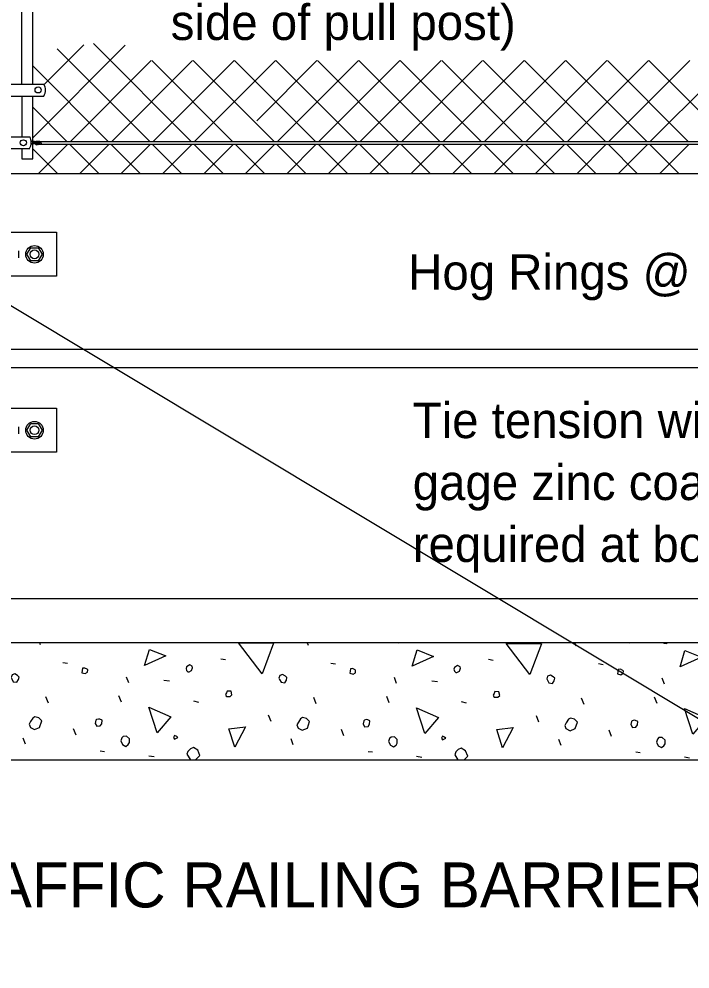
# Model space of a CAD drawing. Extents: x 110698 to 110915, y 110390 to 110472.
# Drawn here: x 110885.02 to 110888.84, y 110456.42 to 110461.82 of the extents above; entities that cross this region are included whole.
import ezdxf

# ---------------------------------------------------------------- set-up
doc = ezdxf.new("R2010")
doc.units = 0
for name, color, linetype in [('Border', 7, 'Continuous'), ('PlotBorder_dp', 7, 'Continuous'), ('SheetBorder_dp', 7, 'Continuous'), ('SheetLines_dp', 7, 'Continuous'), ('SupstrConc_h', 7, 'Continuous'), ('TextMisc', 7, 'Continuous')]:
    doc.layers.add(name, color=color, linetype=linetype)

msp = doc.modelspace()

# ---------------------------------------------------------------- linework, layer by layer
at = {"layer": 'SheetBorder_dp'}
for p, q in [((110885.1002, 110461.1484), (110885.626, 110461.6742)), ((110885.166, 110461.4498), (110885.3915, 110461.6754)), ((110885.2392, 110461.6536), (110885.766, 110461.1268)), ((110885.4454, 110461.6831), (110886.0017, 110461.1268)), ((110885.1002, 110461.5569), (110885.5303, 110461.1268)), ((110885.3143, 110461.1268), (110885.7745, 110461.587)), ((110885.55, 110461.1268), (110886.0102, 110461.587)), ((110885.7773, 110461.587), (110886.2374, 110461.1268)), ((110885.7857, 110461.1268), (110886.2459, 110461.587)), ((110886.013, 110461.587), (110886.4731, 110461.1268)), ((110886.0214, 110461.1268), (110886.4816, 110461.587)), ((110886.2487, 110461.587), (110886.7088, 110461.1268)), ((110886.375, 110461.2446), (110886.7173, 110461.587)), ((110886.4844, 110461.587), (110886.9445, 110461.1268)), ((110886.4928, 110461.1268), (110886.953, 110461.587)), ((110886.7201, 110461.587), (110887.1802, 110461.1268)), ((110886.7285, 110461.1268), (110887.1887, 110461.587)), ((110886.9558, 110461.587), (110887.4159, 110461.1268)), ((110886.9642, 110461.1268), (110887.4244, 110461.587)), ((110887.1915, 110461.587), (110887.6516, 110461.1268)), ((110887.1999, 110461.1268), (110887.6601, 110461.587)), ((110887.4272, 110461.587), (110887.8873, 110461.1268)), ((110887.4356, 110461.1268), (110887.8958, 110461.587)), ((110887.6629, 110461.587), (110888.1231, 110461.1268)), ((110887.6713, 110461.1268), (110888.1315, 110461.587)), ((110887.8986, 110461.587), (110888.3588, 110461.1268)), ((110887.907, 110461.1268), (110888.3672, 110461.587)), ((110888.1343, 110461.587), (110888.5945, 110461.1268)), ((110888.1427, 110461.1268), (110888.6029, 110461.587)), ((110888.37, 110461.587), (110888.8302, 110461.1268)), ((110888.3784, 110461.1268), (110888.8386, 110461.587)), ((110888.6057, 110461.587), (110889.0659, 110461.1268)), ((110888.6141, 110461.1268), (110889.0734, 110461.5861)), ((110885.1002, 110461.3212), (110885.2946, 110461.1268)), ((110885.1329, 110460.9454), (110885.2996, 110461.112)), ((110885.3094, 110461.112), (110885.476, 110460.9454)), ((110885.3686, 110460.9454), (110885.5353, 110461.112)), ((110885.5451, 110461.112), (110885.7117, 110460.9454)), ((110885.6043, 110460.9454), (110885.771, 110461.112)), ((110885.7808, 110461.112), (110885.9474, 110460.9454)), ((110885.84, 110460.9454), (110886.0067, 110461.112)), ((110886.0165, 110461.112), (110886.1831, 110460.9454)), ((110886.0757, 110460.9454), (110886.2424, 110461.112)), ((110886.2522, 110461.112), (110886.4188, 110460.9454)), ((110886.3114, 110460.9454), (110886.4781, 110461.112)), ((110886.4879, 110461.112), (110886.6546, 110460.9454)), ((110886.5471, 110460.9454), (110886.7138, 110461.112)), ((110886.7236, 110461.112), (110886.8903, 110460.9454)), ((110886.7828, 110460.9454), (110886.9495, 110461.112)), ((110886.9593, 110461.112), (110887.126, 110460.9454)), ((110887.0185, 110460.9454), (110887.1852, 110461.112)), ((110887.195, 110461.112), (110887.3617, 110460.9454)), ((110887.2542, 110460.9454), (110887.4209, 110461.112)), ((110887.4307, 110461.112), (110887.5974, 110460.9454)), ((110887.4899, 110460.9454), (110887.6566, 110461.112)), ((110887.6664, 110461.112), (110887.8331, 110460.9454)), ((110887.7256, 110460.9454), (110887.8923, 110461.112)), ((110887.9021, 110461.112), (110888.0688, 110460.9454)), ((110887.9613, 110460.9454), (110888.128, 110461.112)), ((110888.1378, 110461.112), (110888.3045, 110460.9454)), ((110888.197, 110460.9454), (110888.3637, 110461.112)), ((110888.3735, 110461.112), (110888.5402, 110460.9454)), ((110888.4327, 110460.9454), (110888.5994, 110461.112)), ((110888.6092, 110461.112), (110888.7759, 110460.9454)), ((110888.6684, 110460.9454), (110888.8351, 110461.112)), ((110885.1002, 110461.0855), (110885.2403, 110460.9454)), ((110885.145, 110458.2646), (110885.1398, 110458.2787)), ((110886.6689, 110458.261), (110886.6623, 110458.2787)), ((110888.1927, 110458.2575), (110888.1849, 110458.2787)), ((110888.4879, 110458.2787), (110888.495, 110458.2769)), ((110885.2723, 110458.1656), (110885.2988, 110458.1603)), ((110886.1703, 110458.1868), (110886.1969, 110458.1815)), ((110886.7961, 110458.162), (110886.8226, 110458.1567)), ((110887.6942, 110458.1832), (110887.7207, 110458.1779)), ((110888.3199, 110458.1585), (110888.3465, 110458.1532)), ((110885.6471, 110458.0489), (110885.6347, 110458.0825)), ((110885.8468, 110458.0648), (110885.8787, 110458.0613)), ((110887.1709, 110458.0454), (110887.1585, 110458.0789)), ((110887.3707, 110458.0613), (110887.4025, 110458.0577)), ((110888.6947, 110458.0418), (110888.6823, 110458.0754)), ((110885.1892, 110457.934), (110885.1751, 110457.9693)), ((110885.6047, 110457.9393), (110885.5905, 110457.9746)), ((110886.0148, 110457.9464), (110886.0431, 110457.9393)), ((110886.713, 110457.9305), (110886.6989, 110457.9658)), ((110887.1285, 110457.9358), (110887.1143, 110457.9711)), ((110887.5386, 110457.9428), (110887.5669, 110457.9358)), ((110888.2369, 110457.9269), (110888.2227, 110457.9623)), ((110888.6523, 110457.9322), (110888.6381, 110457.9676)), ((110886.4567, 110457.8297), (110886.4426, 110457.865)), ((110887.9805, 110457.8262), (110887.9664, 110457.8615)), ((110885.3466, 110457.7519), (110885.3324, 110457.7873)), ((110886.8704, 110457.7484), (110886.8562, 110457.7837)), ((110888.3942, 110457.7448), (110888.3801, 110457.7802)), ((110885.0584, 110457.7006), (110885.046, 110457.7342)), ((110886.5822, 110457.6971), (110886.5699, 110457.7307)), ((110888.106, 110457.6936), (110888.0937, 110457.7272)), ((110885.4844, 110457.6635), (110885.5092, 110457.66)), ((110887.0083, 110457.66), (110887.033, 110457.6565)), ((110888.5321, 110457.6565), (110888.5568, 110457.6529)), ((110885.7602, 110457.6352), (110885.7903, 110457.6299)), ((110887.284, 110457.6317), (110887.3141, 110457.6264)), ((110888.8078, 110457.6282), (110888.8379, 110457.6229))]:
    msp.add_line(p, q, dxfattribs=at)
for points in [[(110886.4055, 110458.1002), (110886.2711, 110458.2769), (110886.4709, 110458.2752), (110886.4055, 110458.1002)], [(110887.1674, 110458.2787), (110887.1797, 110458.2769), (110887.1839, 110458.2787)], [(110887.9293, 110458.0966), (110887.7949, 110458.2734), (110887.9947, 110458.2716), (110887.9293, 110458.0966)], [(110888.6876, 110458.2787), (110888.6912, 110458.2752)], [(110888.6912, 110458.2752), (110888.7036, 110458.2734), (110888.7159, 110458.2787)], [(110885.7355, 110458.1479), (110885.7638, 110458.2398), (110885.8574, 110458.2027), (110885.7355, 110458.1479)], [(110887.2593, 110458.1444), (110887.2876, 110458.2363), (110887.3813, 110458.1992), (110887.2593, 110458.1444)], [(110888.7831, 110458.1408), (110888.8114, 110458.2327), (110888.9051, 110458.1956), (110888.7831, 110458.1408)], [(110885.983, 110458.1125), (110885.99, 110458.1125), (110886.0042, 110458.1196), (110886.0095, 110458.1355), (110886.0077, 110458.1444), (110885.9936, 110458.1514), (110885.9759, 110458.1408), (110885.9724, 110458.1302), (110885.9759, 110458.1196), (110885.983, 110458.1125)], [(110887.5068, 110458.109), (110887.5138, 110458.109), (110887.528, 110458.1161), (110887.5333, 110458.132), (110887.5315, 110458.1408), (110887.5174, 110458.1479), (110887.4997, 110458.1373), (110887.4962, 110458.1267), (110887.4997, 110458.1161), (110887.5068, 110458.109)], [(110884.9806, 110458.0719), (110884.9895, 110458.056), (110885.0107, 110458.0524), (110885.0195, 110458.0683), (110885.0231, 110458.0825), (110885.0142, 110458.0913), (110884.9983, 110458.1002), (110884.9824, 110458.0949), (110884.9771, 110458.0789), (110884.9806, 110458.0719)], [(110885.3801, 110458.1072), (110885.3996, 110458.1019), (110885.412, 110458.1108), (110885.4137, 110458.1231), (110885.4102, 110458.1267), (110885.3961, 110458.1337), (110885.3837, 110458.132), (110885.3819, 110458.1196), (110885.3801, 110458.1072)], [(110886.5044, 110458.0683), (110886.5133, 110458.0524), (110886.5345, 110458.0489), (110886.5433, 110458.0648), (110886.5469, 110458.0789), (110886.538, 110458.0878), (110886.5221, 110458.0966), (110886.5062, 110458.0913), (110886.5009, 110458.0754), (110886.5044, 110458.0683)], [(110886.904, 110458.1037), (110886.9234, 110458.0984), (110886.9358, 110458.1072), (110886.9376, 110458.1196), (110886.934, 110458.1231), (110886.9199, 110458.1302), (110886.9075, 110458.1284), (110886.9057, 110458.1161), (110886.904, 110458.1037)], [(110888.0283, 110458.0648), (110888.0371, 110458.0489), (110888.0583, 110458.0454), (110888.0672, 110458.0613), (110888.0707, 110458.0754), (110888.0619, 110458.0843), (110888.0459, 110458.0931), (110888.03, 110458.0878), (110888.0247, 110458.0719), (110888.0283, 110458.0648)], [(110888.4278, 110458.1002), (110888.4472, 110458.0949), (110888.4596, 110458.1037), (110888.4614, 110458.1161), (110888.4578, 110458.1196), (110888.4437, 110458.1267), (110888.4313, 110458.1249), (110888.4295, 110458.1125), (110888.4278, 110458.1002)], [(110886.2022, 110457.9711), (110886.2234, 110457.9711), (110886.234, 110457.9817), (110886.2287, 110458.0012), (110886.2057, 110458.0029), (110886.2022, 110457.9923), (110886.1969, 110457.9835), (110886.2022, 110457.9711), (110886.1986, 110457.9746)], [(110887.726, 110457.9676), (110887.7472, 110457.9676), (110887.7578, 110457.9782), (110887.7525, 110457.9976), (110887.7295, 110457.9994), (110887.726, 110457.9888), (110887.7207, 110457.98), (110887.726, 110457.9676), (110887.7224, 110457.9711)], [(110885.8079, 110457.7643), (110885.7602, 110457.911), (110885.8857, 110457.8562), (110885.8079, 110457.7643)], [(110887.3318, 110457.7607), (110887.284, 110457.9075), (110887.4095, 110457.8527), (110887.3318, 110457.7607)], [(110888.8556, 110457.7572), (110888.8078, 110457.9039), (110888.9334, 110457.8491), (110888.8556, 110457.7572)], [(110885.0867, 110457.7961), (110885.1097, 110457.7837), (110885.1397, 110457.7961), (110885.1521, 110457.8332), (110885.1344, 110457.8509), (110885.1114, 110457.8562), (110885.1008, 110457.8491), (110885.0885, 110457.8297), (110885.0796, 110457.8138), (110885.0867, 110457.7961)], [(110885.4562, 110457.8191), (110885.465, 110457.8032), (110885.4844, 110457.8049), (110885.4933, 110457.8173), (110885.4951, 110457.8368), (110885.4827, 110457.8421), (110885.4738, 110457.8438), (110885.4632, 110457.8403), (110885.4597, 110457.8368), (110885.4562, 110457.8191)], [(110886.6105, 110457.7926), (110886.6335, 110457.7802), (110886.6635, 110457.7926), (110886.6759, 110457.8297), (110886.6582, 110457.8474), (110886.6353, 110457.8527), (110886.6247, 110457.8456), (110886.6123, 110457.8262), (110886.6034, 110457.8102), (110886.6105, 110457.7926)], [(110886.98, 110457.8156), (110886.9888, 110457.7996), (110887.0083, 110457.8014), (110887.0171, 110457.8138), (110887.0189, 110457.8332), (110887.0065, 110457.8385), (110886.9977, 110457.8403), (110886.987, 110457.8368), (110886.9835, 110457.8332), (110886.98, 110457.8156)], [(110888.1343, 110457.789), (110888.1573, 110457.7767), (110888.1874, 110457.789), (110888.1997, 110457.8262), (110888.1821, 110457.8438), (110888.1591, 110457.8491), (110888.1485, 110457.8421), (110888.1361, 110457.8226), (110888.1273, 110457.8067), (110888.1343, 110457.789)], [(110888.5038, 110457.812), (110888.5126, 110457.7961), (110888.5321, 110457.7979), (110888.5409, 110457.8102), (110888.5427, 110457.8297), (110888.5303, 110457.835), (110888.5215, 110457.8368), (110888.5109, 110457.8332), (110888.5073, 110457.8297), (110888.5038, 110457.812)], [(110886.2499, 110457.683), (110886.2163, 110457.7873), (110886.31, 110457.7996), (110886.2499, 110457.683)], [(110887.7737, 110457.6794), (110887.7401, 110457.7837), (110887.8338, 110457.7961), (110887.7737, 110457.6794)], [(110885.6011, 110457.7201), (110885.6117, 110457.6989), (110885.6294, 110457.6883), (110885.6435, 110457.6989), (110885.6506, 110457.7095), (110885.6506, 110457.7307), (110885.6347, 110457.7466), (110885.6153, 110457.7448), (110885.6064, 110457.736), (110885.6011, 110457.7201)], [(110885.9069, 110457.7289), (110885.9264, 110457.7378), (110885.9193, 110457.7448), (110885.9069, 110457.7501), (110885.9016, 110457.7378), (110885.9069, 110457.7289)], [(110887.1249, 110457.7166), (110887.1355, 110457.6953), (110887.1532, 110457.6847), (110887.1674, 110457.6953), (110887.1744, 110457.7059), (110887.1744, 110457.7272), (110887.1585, 110457.7431), (110887.1391, 110457.7413), (110887.1302, 110457.7325), (110887.1249, 110457.7166)], [(110887.4308, 110457.7254), (110887.4502, 110457.7342), (110887.4431, 110457.7413), (110887.4308, 110457.7466), (110887.4255, 110457.7342), (110887.4308, 110457.7254)], [(110888.6488, 110457.713), (110888.6594, 110457.6918), (110888.677, 110457.6812), (110888.6912, 110457.6918), (110888.6982, 110457.7024), (110888.6982, 110457.7236), (110888.6823, 110457.7395), (110888.6629, 110457.7378), (110888.6541, 110457.7289), (110888.6488, 110457.713)], [(110886.0269, 110457.612), (110886.0325, 110457.6176), (110886.0519, 110457.637), (110886.0395, 110457.6671), (110886.0148, 110457.6812), (110885.9971, 110457.6741), (110885.983, 110457.66), (110885.9777, 110457.6441)], [(110887.5543, 110457.612), (110887.5563, 110457.614), (110887.5757, 110457.6335), (110887.5633, 110457.6635), (110887.5386, 110457.6777), (110887.5209, 110457.6706), (110887.5068, 110457.6565), (110887.5015, 110457.6405)], [(110885.9777, 110457.6441), (110885.9975, 110457.612)], [(110887.5015, 110457.6405), (110887.5191, 110457.612)]]:
    msp.add_lwpolyline(points, dxfattribs=at)
at = {"layer": 'SheetLines_dp'}
for p, q in [((110866.0939, 110471.5234), (110914.9915, 110442.1849)), ((110884.9752, 110460.9454), (110891.4436, 110460.9454)), ((110884.9752, 110459.9454), (110894.6836, 110459.9454)), ((110884.9752, 110459.8412), (110894.6836, 110459.8412)), ((110873.4424, 110458.2787), (110896.2163, 110458.2787)), ((110873.4424, 110457.612), (110896.2163, 110457.612))]:
    msp.add_line(p, q, dxfattribs=at)
at = {"layer": 'SupstrConc_h'}
msp.add_line((110873.4424, 110458.5287), (110896.2163, 110458.5287), dxfattribs=at)
at = {"layer": 'TextMisc'}
for p, q in [((110885.0377, 110461.4526), (110885.0377, 110462.6654)), ((110885.1002, 110461.4526), (110885.1002, 110462.6654)), ((110884.6737, 110461.4526), (110885.1647, 110461.4526)), ((110884.6737, 110461.3849), (110885.164, 110461.3849)), ((110885.0377, 110461.3849), (110885.0377, 110461.1539)), ((110885.1002, 110461.1299), (110885.1002, 110461.3849)), ((110884.5756, 110461.154), (110885.0834, 110461.154)), ((110885.0907, 110461.1315), (110885.1199, 110461.1269)), ((110885.0908, 110461.1315), (110885.1201, 110461.1269)), ((110885.0912, 110461.111), (110885.1248, 110461.1167)), ((110885.0913, 110461.1264), (110885.1173, 110461.1223)), ((110885.0913, 110461.111), (110885.1249, 110461.1167)), ((110885.0914, 110461.1264), (110885.1174, 110461.1223)), ((110885.0916, 110461.1157), (110885.1215, 110461.1207)), ((110885.0917, 110461.1157), (110885.1216, 110461.1207)), ((110885.1002, 110461.1172), (110885.1002, 110461.125)), ((110885.1002, 110461.1172), (110885.1002, 110461.125)), ((110885.1002, 110461.0287), (110885.1002, 110461.1125)), ((110885.1373, 110461.112), (110894.535, 110461.112)), ((110885.1386, 110461.1268), (110894.5084, 110461.1268)), ((110884.5758, 110461.0861), (110885.0831, 110461.0861)), ((110885.0377, 110461.0861), (110885.0377, 110461.0287)), ((110885.0377, 110461.0287), (110885.1002, 110461.0287)), ((110884.4234, 110460.6103), (110885.2354, 110460.6103)), ((110885.2354, 110460.6103), (110885.2354, 110460.3603)), ((110885.0221, 110460.4658), (110885.0221, 110460.5047)), ((110885.2354, 110460.3603), (110884.4234, 110460.3603)), ((110884.4234, 110459.6103), (110885.2354, 110459.6103)), ((110885.2354, 110459.6103), (110885.2354, 110459.3603)), ((110885.0221, 110459.4658), (110885.0221, 110459.5047)), ((110885.2354, 110459.3603), (110884.4234, 110459.3603))]:
    msp.add_line(p, q, dxfattribs=at)
for points in [[(110885.0887, 110460.5228), (110885.132, 110460.5228), (110885.1537, 110460.4853), (110885.132, 110460.4477), (110885.0887, 110460.4477), (110885.067, 110460.4853)], [(110885.0887, 110459.5228), (110885.132, 110459.5228), (110885.1537, 110459.4853), (110885.132, 110459.4477), (110885.0887, 110459.4477), (110885.067, 110459.4853)]]:
    msp.add_lwpolyline(points, close=True, dxfattribs=at)
for centre, radius in [((110885.1104, 110460.4853), 0.05), ((110885.1104, 110460.4853), 0.025), ((110885.1104, 110459.4853), 0.05), ((110885.1104, 110459.4853), 0.025)]:
    msp.add_circle(centre, radius, dxfattribs=at)
for centre, major_axis in [((110885.131, 110461.4198), (-0.0177, 0)), ((110885.0474, 110461.1194), (-0.0178, 0)), ((110885.0474, 110461.1194), (-0.0178, 0))]:
    msp.add_ellipse(centre, major_axis=major_axis, ratio=0.957868, dxfattribs=at)
for centre, major_axis, ratio, start_param, end_param in [((110885.0951, 110461.4194), (0.0776, 0), 0.957868, 5.800651, 6.745353), ((110885.014, 110461.1203), (0.0776, 0), 0.957868, 5.803915, 6.752041), ((110885.014, 110461.1203), (0.0776, 0), 0.957868, 5.803915, 6.752041), ((110885.1225, 110461.117), (-0.0095, 0), 0.957868, 5.673972, 6.052579), ((110885.1225, 110461.117), (-0.0095, 0), 0.957868, 5.673972, 6.052579), ((110885.1225, 110461.117), (-0.0095, 0), 0.957868, 0.252467, 1.271421), ((110885.1225, 110461.117), (-0.0095, 0), 0.957868, 0.252467, 1.271421), ((110885.1166, 110461.1128), (0.00982, 0), 0.957868, 0.655696, 1.505671), ((110885.1166, 110461.1128), (0.00982, 0), 0.957868, 0.655696, 1.505671), ((110885.1185, 110461.1177), (0.0115, -0.0041), 0.737732, 5.08821, 8.212701), ((110885.1185, 110461.1177), (0.0115, -0.0041), 0.737732, 5.08821, 8.212701), ((110885.1219, 110461.1152), (0.00301, 0), 0.957868, 3.28349, 5.170635), ((110885.1219, 110461.1152), (0.00301, 0), 0.957868, 3.28349, 5.170635), ((110885.1225, 110461.1174), (-0.00453, 0), 0.957868, 5.149727, 5.551998), ((110885.1225, 110461.1174), (-0.00453, 0), 0.957868, 5.149727, 5.551998), ((110885.1198, 110461.1161), (0.00527, 0), 0.957868, 5.058829, 7.342751), ((110885.1198, 110461.1161), (0.00527, 0), 0.957868, 5.058829, 7.342751), ((110885.1242, 110461.1185), (-0.00872, 0), 0.957868, 2.1008, 4.992926), ((110885.1242, 110461.1185), (-0.00872, 0), 0.957868, 2.1008, 4.992926), ((110885.1219, 110461.1152), (0.00301, 0), 0.957868, 0.004594, 0.141897), ((110885.1219, 110461.1152), (0.00301, 0), 0.957868, 0.004594, 0.141897), ((110885.1303, 110461.1181), (0.00944, 0), 0.957868, 4.316497, 6.557353), ((110885.1303, 110461.1181), (0.00944, 0), 0.957868, 4.316497, 6.557353), ((110885.1307, 110461.1191), (-0.00872, 0), 0.957868, 3.323334, 4.992926), ((110885.1307, 110461.1191), (-0.00872, 0), 0.957868, 3.323334, 4.992926), ((110885.1307, 110461.1191), (-0.00503, 0), 0.92697, 1.780895, 4.712389), ((110885.1307, 110461.1191), (-0.00503, 0), 0.92697, 1.780895, 4.712389), ((110885.1355, 110461.1136), (-0.0142, 0), 0.957868, 3.141593, 4.79635), ((110885.1355, 110461.1136), (-0.0142, 0), 0.957868, 3.141593, 4.79635), ((110885.1274, 110461.0985), (0.0274, 0), 0.957868, 0.628521, 1.149654), ((110885.1274, 110461.0985), (0.0274, 0), 0.957868, 0.628521, 1.149654)]:
    msp.add_ellipse(centre, major_axis=major_axis, ratio=ratio, start_param=start_param, end_param=end_param, dxfattribs=at)

# ---------------------------------------------------------------- texts
at = {"layer": 'Border'}
for s, height, p in [('Hog Rings @ 2\'-0" Centers', 0.2016, (110887.2365, 110460.2839)), ('PULL POST ASSEMBLY DETAIL FOR TRAFFIC RAILING BARRIERS', 0.256001, (110878.3805, 110456.7727))]:
    msp.add_text(s, height=height, dxfattribs=at).set_placement(p)
at = {"layer": 'PlotBorder_dp'}
for s, p in [('side of pull post)', (110885.8855, 110461.7036)), ('Tie tension wire to post with No. 9 ', (110887.2624, 110459.4405)), ('gage zinc coated tie wire (triple wrap ', (110887.2624, 110459.0885)), ('required at both ends of tie wire) (Typ.)', (110887.2624, 110458.7365))]:
    msp.add_text(s, height=0.2016, dxfattribs=at).set_placement(p)

doc.saveas('drawing.dxf')
